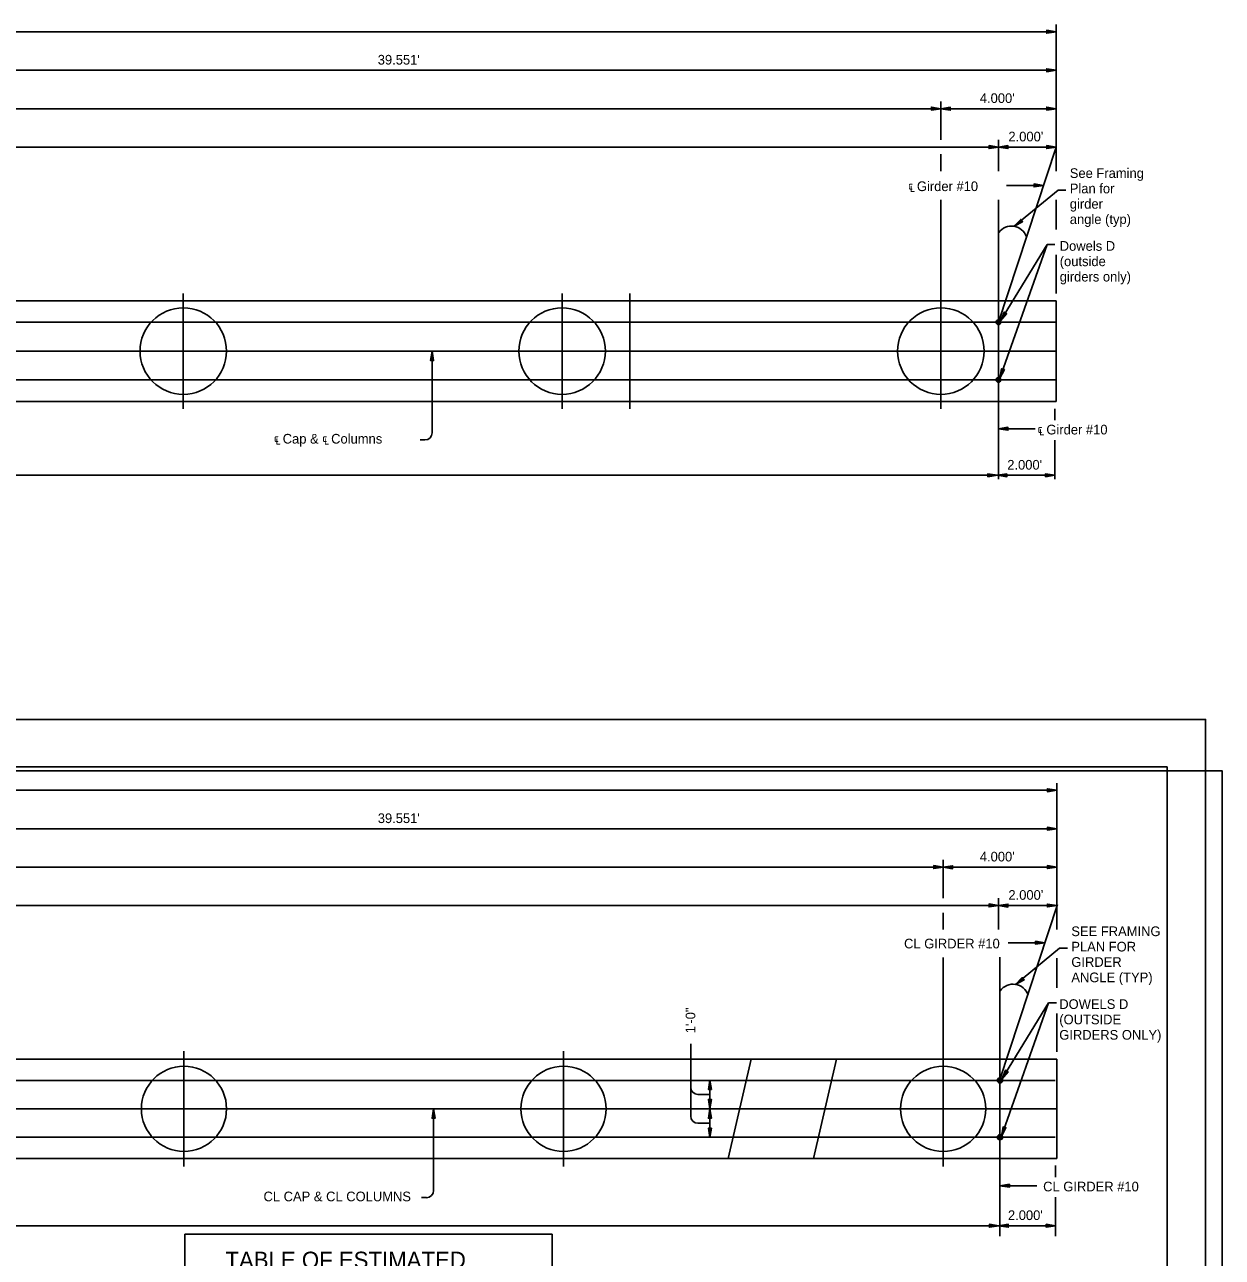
# Model space of a CAD drawing. Extents: x 1000 to 1084.3, y 977.1 to 1031.2.
# Drawn here: x 1018.63 to 1034.22, y 1015 to 1031.04 of the extents above; entities that cross this region are included whole.
import ezdxf

# ---------------------------------------------------------------- set-up
doc = ezdxf.new("R2010")
doc.units = 0
for name, color, linetype in [('Bent', 7, 'Continuous'), ('BORD_lines_major', 7, 'Continuous'), ('BreakLine', 7, 'Continuous'), ('D_BATCH_PLOT', 7, 'Continuous'), ('D_SHEET', 7, 'Continuous'), ('DILLED SHAFTS', 7, 'Continuous'), ('Working Level 1', 7, 'Continuous')]:
    doc.layers.add(name, color=color, linetype=linetype)

msp = doc.modelspace()

# ---------------------------------------------------------------- linework, layer by layer
at = {"layer": 'Bent'}
for p, q in [((1032.062, 1017.576), (1004.405, 1017.576)), ((1028.085, 1017.576), (1027.786, 1016.283)), ((1029.194, 1017.576), (1028.895, 1016.283)), ((1032.062, 1016.283), (1032.062, 1017.576)), ((1027.936, 1016.929), (1029.044, 1016.929)), ((1032.062, 1016.283), (1004.405, 1016.283))]:
    msp.add_line(p, q, dxfattribs=at)
at = {"layer": 'BORD_lines_major'}
for p in [(1002.413, 1021.382), (1033.5, 1000.5)]:
    msp.add_line(p, (1033.5, 1021.382), dxfattribs=at)
at = {"layer": 'BreakLine'}
msp.add_lwpolyline([(1000.939, 1021.329), (1034.217, 1021.329), (1034.217, 1012.016), (1000.939, 1012.016)], close=True, dxfattribs=at)
at = {"layer": 'D_BATCH_PLOT'}
msp.add_lwpolyline([(1000, 1000), (1034, 1000), (1034, 1022), (1000, 1022)], close=True, dxfattribs=at)
at = {"layer": 'D_SHEET'}
for p in [(1000, 1022), (1034, 1000)]:
    msp.add_line(p, (1034, 1022), dxfattribs=at)
at = {"layer": 'DILLED SHAFTS'}
for centre, radius in [((1020.703, 1016.93), 0.554), ((1025.643, 1016.93), 0.554), ((1030.584, 1016.929), 0.554), ((1031.323, 1017.299), 0.0339), ((1031.323, 1017.299), 0.0271), ((1031.323, 1017.299), 0.0203), ((1031.323, 1017.299), 0.0136), ((1031.323, 1017.299), 0.00678), ((1031.323, 1016.56), 0.0339), ((1031.323, 1016.56), 0.0271), ((1031.323, 1016.56), 0.0203), ((1031.323, 1016.56), 0.0136), ((1031.323, 1016.56), 0.00678)]:
    msp.add_circle(centre, radius, dxfattribs=at)
at = {"layer": 'Working Level 1'}
for p, q in [((1004.405, 1030.95), (1032.054, 1030.95)), ((1032.054, 1029.138), (1032.054, 1031.044)), ((1004.405, 1030.45), (1032.054, 1030.45)), ((1002.653, 1029.95), (1032.054, 1029.95)), ((1030.554, 1029.544), (1030.554, 1030.044)), ((1030.554, 1029.544), (1030.554, 1030.044)), ((1002.487, 1029.45), (1032.054, 1029.45)), ((1031.304, 1029.138), (1031.304, 1029.544)), ((1031.304, 1027.169), (1032.054, 1029.45)), ((1030.554, 1029.138), (1030.554, 1029.356)), ((1031.409, 1028.95), (1031.889, 1028.95)), ((1031.508, 1028.419), (1032.079, 1028.89)), ((1032.079, 1028.89), (1032.18, 1028.89)), ((1030.554, 1026.044), (1030.554, 1028.763)), ((1031.304, 1026.045), (1031.304, 1028.763)), ((1032.054, 1028.379), (1032.054, 1028.763)), ((1031.936, 1028.181), (1031.322, 1026.443)), ((1031.328, 1027.187), (1031.936, 1028.181)), ((1031.936, 1028.181), (1032.037, 1028.181)), ((1032.054, 1027.544), (1032.054, 1028.046)), ((1020.694, 1026.044), (1020.694, 1027.544)), ((1025.624, 1026.044), (1025.624, 1027.544)), ((1026.507, 1026.044), (1026.507, 1027.544)), ((1004.405, 1027.45), (1032.054, 1027.45)), ((1032.054, 1026.138), (1032.054, 1027.45)), ((1004.405, 1027.169), (1032.054, 1027.169)), ((1003.499, 1026.794), (1032.054, 1026.794)), ((1023.933, 1025.731), (1023.933, 1026.794)), ((1004.405, 1026.419), (1032.054, 1026.419)), ((1004.405, 1026.138), (1032.054, 1026.138)), ((1031.304, 1025.127), (1031.304, 1026.045)), ((1032.039, 1025.894), (1032.039, 1026.044)), ((1031.783, 1025.782), (1031.304, 1025.782)), ((1023.777, 1025.638), (1023.839, 1025.638)), ((1032.039, 1025.128), (1032.039, 1025.634)), ((1002.811, 1025.177), (1032.039, 1025.177)), ((1032.062, 1019.264), (1032.062, 1021.17)), ((1004.413, 1021.076), (1032.062, 1021.076)), ((1004.405, 1020.576), (1032.054, 1020.576)), ((1030.584, 1019.67), (1030.584, 1020.17)), ((1002.653, 1020.076), (1032.054, 1020.076)), ((1031.304, 1019.264), (1031.304, 1019.67)), ((1002.487, 1019.577), (1032.054, 1019.577)), ((1031.323, 1017.31), (1032.073, 1019.591)), ((1030.584, 1019.264), (1030.584, 1019.483)), ((1031.429, 1019.091), (1031.909, 1019.091)), ((1031.527, 1018.549), (1032.098, 1019.02)), ((1032.098, 1019.02), (1032.2, 1019.02)), ((1030.584, 1016.179), (1030.584, 1018.898)), ((1031.323, 1016.186), (1031.323, 1018.904)), ((1032.062, 1018.505), (1032.062, 1018.889)), ((1031.955, 1018.311), (1031.342, 1016.573)), ((1031.347, 1017.317), (1031.955, 1018.311)), ((1031.955, 1018.311), (1032.057, 1018.311)), ((1032.062, 1017.67), (1032.062, 1018.172)), ((1027.298, 1016.836), (1027.298, 1017.776)), ((1020.703, 1016.18), (1020.703, 1017.68)), ((1025.643, 1016.18), (1025.643, 1017.68)), ((1004.394, 1017.299), (1032.043, 1017.299)), ((1027.548, 1016.555), (1027.548, 1017.305)), ((1027.392, 1017.117), (1027.548, 1017.117)), ((1003.499, 1016.93), (1032.054, 1016.93)), ((1023.952, 1015.867), (1023.952, 1016.93)), ((1027.392, 1016.742), (1027.548, 1016.742)), ((1004.394, 1016.56), (1032.043, 1016.56)), ((1031.323, 1015.273), (1031.323, 1016.19)), ((1032.047, 1016.04), (1032.047, 1016.19)), ((1031.803, 1015.928), (1031.323, 1015.928)), ((1023.796, 1015.774), (1023.858, 1015.774)), ((1032.047, 1015.273), (1032.047, 1015.78)), ((1002.811, 1015.408), (1032.039, 1015.408)), ((1020.713, 1010.097), (1020.713, 1015.297)), ((1020.713, 1015.297), (1025.494, 1015.297)), ((1025.494, 1010.097), (1025.494, 1015.297))]:
    msp.add_line(p, q, dxfattribs=at)
for points in [[(1032.054, 1030.95), (1031.931, 1030.97), (1031.931, 1030.931)], [(1032.054, 1030.45), (1031.931, 1030.47), (1031.931, 1030.431)], [(1030.554, 1029.95), (1030.431, 1029.97), (1030.431, 1029.931)], [(1030.554, 1029.95), (1030.676, 1029.93), (1030.676, 1029.969)], [(1032.054, 1029.95), (1031.931, 1029.97), (1031.931, 1029.931)], [(1031.304, 1029.45), (1031.181, 1029.47), (1031.181, 1029.431)], [(1031.304, 1029.45), (1031.426, 1029.43), (1031.426, 1029.469)], [(1032.054, 1029.45), (1031.931, 1029.47), (1031.931, 1029.431)], [(1031.889, 1028.95), (1031.767, 1028.97), (1031.767, 1028.931)], [(1031.508, 1028.419), (1031.617, 1028.477), (1031.594, 1028.508)], [(1031.328, 1027.187), (1031.409, 1027.281), (1031.376, 1027.302)], [(1023.933, 1026.794), (1023.913, 1026.671), (1023.952, 1026.671)], [(1031.322, 1026.443), (1031.381, 1026.553), (1031.344, 1026.565)], [(1031.304, 1025.782), (1031.426, 1025.802), (1031.426, 1025.763)], [(1031.289, 1025.177), (1031.166, 1025.197), (1031.166, 1025.158)], [(1031.289, 1025.177), (1031.411, 1025.157), (1031.411, 1025.196)], [(1032.039, 1025.177), (1031.916, 1025.197), (1031.916, 1025.158)], [(1032.062, 1021.076), (1031.94, 1021.096), (1031.94, 1021.058)], [(1032.062, 1020.576), (1031.94, 1020.596), (1031.94, 1020.558)], [(1030.584, 1020.076), (1030.462, 1020.096), (1030.462, 1020.058)], [(1030.584, 1020.076), (1030.707, 1020.056), (1030.707, 1020.095)], [(1032.062, 1020.076), (1031.94, 1020.096), (1031.94, 1020.058)], [(1031.304, 1019.577), (1031.181, 1019.597), (1031.181, 1019.558)], [(1031.304, 1019.577), (1031.426, 1019.557), (1031.426, 1019.595)], [(1032.062, 1019.576), (1031.94, 1019.596), (1031.94, 1019.558)], [(1031.909, 1019.091), (1031.786, 1019.111), (1031.786, 1019.072)], [(1031.527, 1018.549), (1031.637, 1018.607), (1031.613, 1018.638)], [(1031.347, 1017.317), (1031.428, 1017.411), (1031.395, 1017.432)], [(1027.548, 1017.305), (1027.528, 1017.182), (1027.567, 1017.182)], [(1023.952, 1016.93), (1023.932, 1016.807), (1023.971, 1016.807)], [(1027.548, 1016.93), (1027.528, 1016.807), (1027.567, 1016.807)], [(1027.548, 1016.93), (1027.568, 1017.052), (1027.529, 1017.052)], [(1027.548, 1016.555), (1027.568, 1016.677), (1027.529, 1016.677)], [(1031.342, 1016.573), (1031.4, 1016.683), (1031.363, 1016.695)], [(1031.323, 1015.928), (1031.446, 1015.948), (1031.446, 1015.909)], [(1031.308, 1015.408), (1031.186, 1015.428), (1031.186, 1015.389)], [(1031.308, 1015.408), (1031.431, 1015.388), (1031.431, 1015.427)], [(1032.047, 1015.408), (1031.925, 1015.428), (1031.925, 1015.389)]]:
    msp.add_lwpolyline(points, close=True, dxfattribs=at)
for centre, radius in [((1020.694, 1026.794), 0.563), ((1025.624, 1026.794), 0.563), ((1030.554, 1026.794), 0.563), ((1031.304, 1027.169), 0.0306), ((1031.304, 1027.169), 0.0245), ((1031.304, 1027.169), 0.0183), ((1031.304, 1027.169), 0.0122), ((1031.304, 1027.169), 0.00611), ((1031.304, 1026.419), 0.0306), ((1031.304, 1026.419), 0.0245), ((1031.304, 1026.419), 0.0183), ((1031.304, 1026.419), 0.0122), ((1031.304, 1026.419), 0.00611)]:
    msp.add_circle(centre, radius, dxfattribs=at)
for centre, radius, start, end in [((1031.473, 1028.216), 0.206, 18.6635, 143.8717), ((1023.839, 1025.731), 0.0938, 270, 0), ((1031.493, 1018.346), 0.206, 18.6635, 143.8717), ((1027.392, 1017.211), 0.0938, 180, 270), ((1027.392, 1016.836), 0.0938, 180, 270), ((1023.858, 1015.867), 0.0938, 270, 0)]:
    msp.add_arc(centre, radius, start, end, dxfattribs=at)

# ---------------------------------------------------------------- texts
for s, height, p in [("39.551'", 0.126, (1023.225, 1030.524)), ("4.000'", 0.126, (1031.061, 1030.024)), ("2.000'", 0.126, (1031.433, 1029.524)), ('See Framing ', 0.126, (1032.232, 1029.048)), ('℄ Girder #10', 0.126, (1030.127, 1028.877)), ('Plan for ', 0.126, (1032.232, 1028.848)), ('girder ', 0.126, (1032.232, 1028.648)), ('angle (typ)', 0.126, (1032.232, 1028.448)), ('Dowels D', 0.126, (1032.101, 1028.1)), ('(outside', 0.126, (1032.101, 1027.9)), ('girders only)', 0.126, (1032.101, 1027.7)), ('℄ Girder #10', 0.126, (1031.812, 1025.709)), ('℄ Cap & ℄ Columns', 0.126, (1021.873, 1025.59)), ("2.000'", 0.126, (1031.418, 1025.251)), ("39.551'", 0.126, (1023.225, 1020.65)), ("4.000'", 0.126, (1031.061, 1020.15)), ("2.000'", 0.126, (1031.433, 1019.651)), ('SEE FRAMING ', 0.126, (1032.252, 1019.178)), ('CL GIRDER #10', 0.126, (1030.075, 1019.018)), ('PLAN FOR ', 0.126, (1032.252, 1018.978)), ('GIRDER ', 0.126, (1032.252, 1018.778)), ('ANGLE (TYP)', 0.126, (1032.252, 1018.578)), ('DOWELS D', 0.126, (1032.095, 1018.23)), ('(OUTSIDE', 0.126, (1032.095, 1018.03)), ('GIRDERS ONLY)', 0.126, (1032.095, 1017.83)), ('CL GIRDER #10', 0.126, (1031.885, 1015.855)), ('CL CAP & CL COLUMNS', 0.126, (1021.738, 1015.726)), ("2.000'", 0.126, (1031.427, 1015.482)), ('TABLE OF ESTIMATED', 0.216, (1021.242, 1014.854))]:
    msp.add_text(s, height=height, dxfattribs=at).set_placement(p)
msp.add_text('1\'-0"', height=0.126, rotation=90, dxfattribs=at).set_placement((1027.358, 1017.913))

doc.saveas('drawing.dxf')
